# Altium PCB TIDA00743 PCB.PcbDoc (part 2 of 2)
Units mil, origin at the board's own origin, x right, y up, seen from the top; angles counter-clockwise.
Board outline 2110 x 1665 mil, 6 copper layers (Layer 1 - Top Layer, Layer 2 - GND, Layer 3 - Sensitive, Layer 4 - PWR, Layer 5 - GND, Layer 6 - Bottom Layer), stack 59.268 mil thick; 144 components, 87 nets, 420 pads, 309 vias.
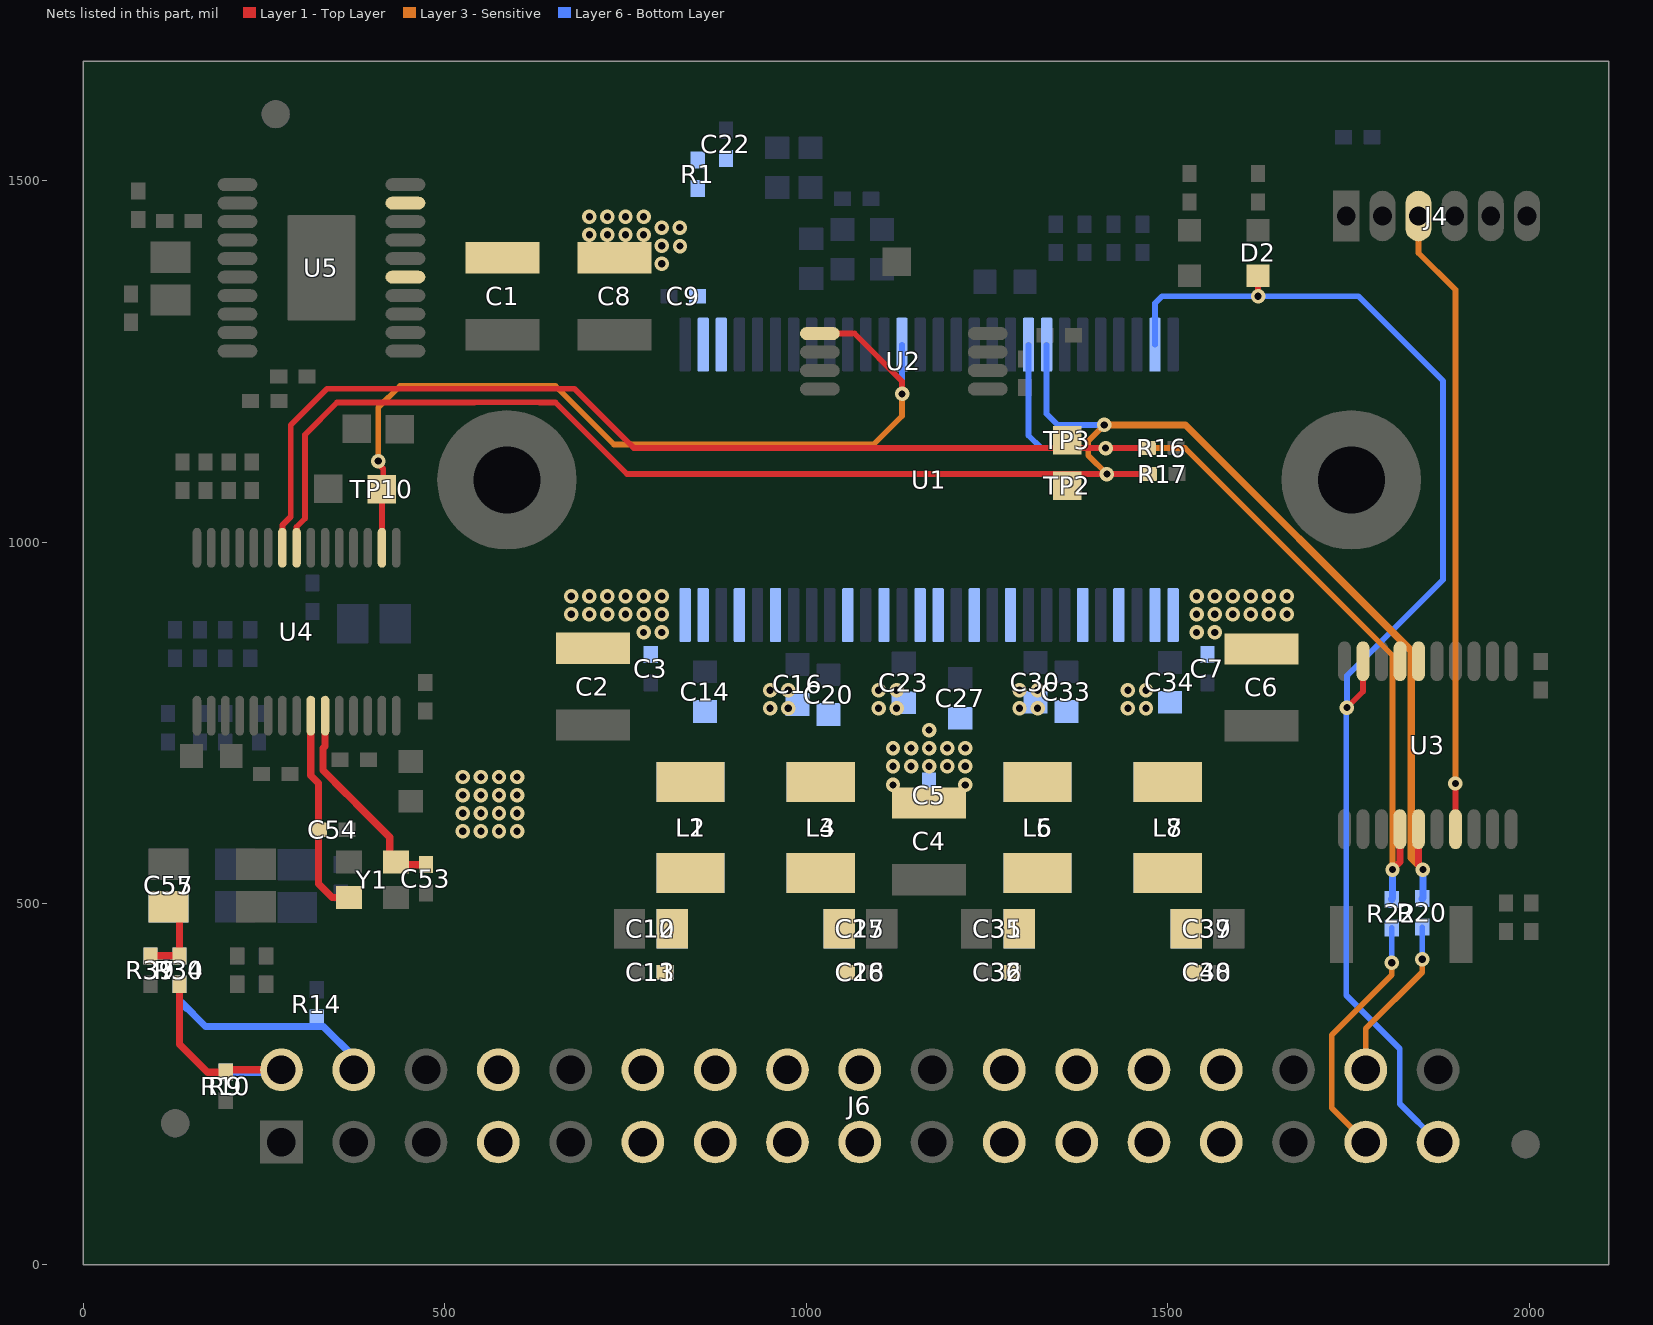
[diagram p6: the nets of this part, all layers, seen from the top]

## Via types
v1: diameter 20, hole 10, Layer 1 - Top Layer to Layer 6 - Bottom Layer, tented both sides, 287 vias
v2: diameter 39.37, hole 19.68, Layer 1 - Top Layer to Layer 6 - Bottom Layer, 12 vias
v3: diameter 19.68, hole 7.87, Layer 1 - Top Layer to Layer 6 - Bottom Layer, 6 vias
v4: diameter 20, hole 10, Layer 1 - Top Layer to Layer 6 - Bottom Layer, tented bottom, 4 vias

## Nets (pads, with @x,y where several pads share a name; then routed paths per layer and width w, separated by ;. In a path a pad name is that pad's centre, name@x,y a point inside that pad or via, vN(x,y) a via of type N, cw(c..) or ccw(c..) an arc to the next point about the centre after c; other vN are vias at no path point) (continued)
NWARN1: D2.1 J6.33 U1.27 U3.9 | length 1769.9
  Layer 1 - Top Layer w8: v1(1625,1340) D2.1@1625,1368.5 ; v1(1748,771) 1770.12,793.12 U3.9@1770.12,835.14
  Layer 6 - Bottom Layer w8: U1.27@1482.5,1273.01 1482.5,1330.5 1492,1340 v1(1625,1340) 1764,1340 1881,1223 1881,948 1748,815 v1(1748,771) ; v1@1747,770 1747,373 1821,299 1821,223.04 J6.33@1874.04,170
OUT1+: C37.1 C38.1 J6.25 J6.26 L7.2
OUT1-: C39.1 C40.1 J6.27 J6.28 L8.2
OUT1M: C34.1 L8.1 U1.32
  other v1: 1445,770 1470,770 1445,795 1470,795
OUT1P: C33.1 L7.1 U1.34
OUT2+: C31.1 C32.1 J6.21 J6.22 L5.2
OUT2-: C35.1 C36.1 J6.23 J6.24 L6.2
OUT2M: C30.1 L6.1 U1.38
  other v1: 1295,770 1320,770 1295,795 1320,795
OUT2P: C27.1 L5.1 U1.40
OUT3+: C17.1 C18.1 J6.15 J6.16 L3.2
OUT3-: C25.1 C26.1 J6.17 J6.18 L4.2
OUT3M: C23.1 L4.1 U1.45
  other v1: 1100,770 1125,770 1100,795 1125,795
OUT3P: C20.1 L3.1 U1.47
OUT4+: C10.1 C11.1 J6.11 J6.12 L1.2
OUT4-: C12.1 C13.1 J6.13 J6.14 L2.2
OUT4M: C16.1 L2.1 U1.51
  other v1: 950,770 975,770 950,795 975,795
OUT4P: C14.1 L1.1 U1.53
PVDD: C1.1 C2.1 C3.1 C4.1 C5.1 C6.1 C7.1 C8.1 C9.1 J6.7 J6.8 R1.1 U1.2 U1.29 U1.30 U1.42 U1.43 U1.55 U1.56 U5.15 U5.19
  other v1: 525,600 550,600 575,600 600,600 525,625 550,625 575,625 600,625 525,650 550,650 575,650 600,650 1120,664 1220,664 525,675 550,675 575,675 600,675 1120,690 1145,690 1170,690 1195,690 1220,690 1120,715 1145,715 1170,715 1195,715 1220,715 1170,740 775,875 800,875 1540,875 1565,875 675,900 700,900 725,900 750,900 775,900 800,900 1540,900 1565,900 1590,900 1615,900 1640,900 1665,900 675,925 700,925 725,925 750,925 775,925 800,925 1540,925 1565,925 1590,925 1615,925 1640,925 1665,925 800,1385 800,1410 825.39,1409.51 700,1425 725,1425 750,1425 775,1425 800,1435 825,1435 700,1450 725,1450 750,1450 775,1450
REAR_L: J6.2 R9.2 R10.2 R30.2 | length 313.8
  Layer 1 - Top Layer w10: R30.2@133,388.31 133,305.31 171.63,266.69 R9.2@197,266.69 ; R9.2@197,270 J6.2@274.04,270
  Layer 6 - Bottom Layer w10: R10.2@197,266.69 J6.2@270.73,266.69
REAR_L_ATTN: C55.1 R30.1 R37.2 | length 114
  Layer 1 - Top Layer w10: R37.2@93,427.69 R30.1@133,427.68 133,480.47 C55.1@118,495.47
REAR_R: J6.4 R14.1 R34.2 | length 328.8
  Layer 6 - Bottom Layer w10: 136,363 169,330 332,330 374.04,287.96 J6.4@374.04,270 ; R34.2@136,385.31 R34.2@133,388.31 133,365 143,355
REAR_R_ATTN: C57.1 R34.1 R39.2 | length 114
  Layer 6 - Bottom Layer w10: R39.2@93,427.69 R34.1@133,427.68 133,480.47 C57.1@118,495.47
SBWTCK: J4.3 U3.17 | length 869.3
  Layer 1 - Top Layer w8: v1(1898,666) 1898.07,665.93 U3.17@1898.07,602.86
  Layer 3 - Sensitive w8: J4.3@1847,1451 1847,1400 1898,1349 v1(1898,666)
SCL: R16.1 R22.2 TP3.1 U1.20 U3.14 U4.24 | length 2569
  Layer 1 - Top Layer w8: U4.24@275.31,992.14 275.31,1023.31 287,1035 287,1162 337,1212 679.4,1212 761.4,1130 v1(1414,1130) R16.1@1472.32,1130
  Layer 1 - Top Layer w10: v1(1811,547) 1821.3,557.3 U3.14@1821.3,602.86
  Layer 3 - Sensitive w8: v1@1415,1131 v1(1414,1130) 1524,1130 1811,843 v1(1811,547)
  Layer 6 - Bottom Layer w8: U1.20@1307.5,1273.01 1307.5,1147.5 1325,1130 v1(1414,1130)
  Layer 6 - Bottom Layer w10: R22.2@1810,505.79 1811,506.79 v1(1811,547)
SCL_EXT: J6.31 R22.1 | length 357.3
  Layer 3 - Sensitive w8: J6.31@1779,174.96 J6.31@1774.04,170 1727,217.04 1727,318 1810,401 v1(1810,418)
  Layer 6 - Bottom Layer w8: v1(1810,418) R22.1@1810,466.42
SCLK: TP10.1 U1.13 U2.1 U4.17 | length 1237.8
  Layer 1 - Top Layer w8: v4@408,1108.49 415,1101.49 415,1075 TP10.1@413.11,1073.11 U4.17@413.11,992.14 ; U2.1@1018.86,1288.39 1066.61,1288.39 1132.5,1222.5 v1(1132.5,1205)
  Layer 3 - Sensitive w8: v4(408,1112) 408,1186 438,1216 653,1216 734,1135 1093,1135 1132.5,1174.5 v1(1132.5,1205)
  Layer 6 - Bottom Layer w8: v1(1132.5,1205) U1.13@1132.5,1273.01
SDA: R17.1 R20.2 TP2.1 U1.21 U3.15 U4.23 | length 2619.8
  Layer 1 - Top Layer w8: U4.23@295,992.14 295,1021 306.5,1032.5 306.5,1148.5 351,1193 541.03,1193 541.49,1193.46 630.51,1193.46 630.97,1193 653,1193 752,1094 v1(1416,1094) R17.1@1473.32,1094
  Layer 1 - Top Layer w10: U3.15@1846.89,602.86 1846.89,553.11 v1(1853,547)
  Layer 3 - Sensitive w8: 1390.15,1140 1390.15,1119.85 v1(1416,1094) ; 1390.45,1139.75 1390.45,1140.3 v1(1412.12,1161.98)
  Layer 3 - Sensitive w10: v1(1412.12,1161.98) 1524.64,1161.98 1837,849.62 1837,563 v1(1853,547)
  Layer 6 - Bottom Layer w8: U1.21@1332.5,1273.01 1332.5,1177.5 1348.02,1161.98 v1(1412.12,1161.98)
  Layer 6 - Bottom Layer w10: R20.2@1852,506.69 1853,507.69 v1(1853,547)
SDA_EXT: J6.32 R20.1 | length 229.6
  Layer 3 - Sensitive w8: J6.32@1774.04,270 1774.04,327.04 1852,405 v1(1852,423)
  Layer 6 - Bottom Layer w8: v1(1852,423) R20.1@1852,467.32
U1_VBAT: C22.1 R1.2 U1.3
VOL_DN: U3.7
VOL_UP: U3.6
XI: C53.1 U4.10 Y1.1 | length 283.1
  Layer 1 - Top Layer w10: U4.10@334.37,759.86 334.37,717.65 331.5,714.79 331.5,684.19 363.69,652 364.11,652 377,639.11 377,638.69 424,591.69 424,566.09 Y1.1@432.48,557.61 ; Y1.1@436.4,553.68 C53.1@474,553.68
XO: C54.1 U4.9 Y1.3 | length 285.3
  Layer 1 - Top Layer w10: U4.9@314.5,758.08 314.5,677.15 325.32,666.33 C54.1@325.32,602 325.32,527.28 344.2,508.39 Y1.3@367.52,508.39
pads on no net: FID1.1 FID2.1 FID3.1 FID4.1 FID5.1 FID6.1 J4.1 J4.6 U3.2 U3.3 U3.4 U3.5 U3.12 U3.13 U3.18 U3.19 U4.5 U4.19 U4.20 U4.22 U5.1 U5.2 U5.5 U5.6 U5.16 U5.17 U5.18 U5.20

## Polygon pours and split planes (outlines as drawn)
GND on Layer 4 - PWR "Layer 4 - PWR - GND" (solid, remove dead copper, pour order 23): 0,0 2110,0 2110,1665 0,1665
PVDD on Layer 4 - PWR "Layer 4 - PWR - PVDD" (solid, pour order 13): 505,584 620,584 620,669 811,860 970,860 1010,820 1010,745 1099,656 1321,656 1410,745 1410,825 1445,860 1655,860 1675,880 1675,945 1600,1020 1040,1020 895,1165 875,1185 875,1210 875,1430 845,1460 690,1460 690,1350 690,1038 505,853
GND on Layer 2 - GND "Layer 2 - GND - GND" (solid, remove dead copper, pour order 21): 0,0 2110,0 2110,1665 0,1665
GND on Layer 5 - GND "Layer 2 - GND - GND" (solid, remove dead copper, pour order 19): 0,0 2110,0 2110,1665 0,1665
+3P3V on Layer 3 - Sensitive "+3P3V_L03_P010" (solid, remove dead copper, pour order 10): 517,982 517,952 461,952 445.02,936.02 445.02,982
GND on Layer 3 - Sensitive "Layer 3 - Sensitive - GND" (solid, remove dead copper, pour order 17): 0,0 2110,0 2110,1665 0,1665
GND on Layer 1 - Top Layer "Layer 1 - Top Layer - GND" (solid, remove dead copper, pour order 15): 0,0 2110,0 2110,1665 0,1665
3V3_OUT on Layer 1 - Top Layer "3V3_OUT_L01_P009" (solid, remove dead copper, pour order 9): 198,1419 88.85,1419 88.85,1458 54,1458 54,1419 54,1372 54,1332 82,1332 82,1372 147,1372 184,1409 198,1409
GND on Layer 6 - Bottom Layer "Layer 6 - Bottom Layer - GND" (solid, remove dead copper, pour order 14): 0,0 2110,0 2110,1665 0,1665
PVDD on Layer 6 - Bottom Layer "PVDD_L06_P012" (solid, remove dead copper, pour order 12): 815.21,855.09 658,855 658,960 701,1003 701,1128 634.86,1194.14 634.86,1420.55 690,1460 824.51,1460 825,1460.49 825,1399.9 793.1,1368 725,1368 725,1189.63 816,1180 816,1098.63 816,855.89

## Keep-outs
Keep-Out Layer:
  text ".Layer_Name" at 97,-758.49 h60

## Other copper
Layer 1 - Top Layer:
  rectangle net PVDD: 1149,757 1191,872.74
  region net +3P3V: 55.45,1314.74 55.45,1253.91 63.36,1246 112,1246 116,1250 116,1262 109,1269 86.18,1269 77.79,1277.39 77.79,1290.3 77.79,1318 55.45,1318
  pour cut-out: 0,1166 255.63,1166 255.63,1038.14 240.24,1022.76 230,1012.51 230,951.45 249.45,932 252,932 252,846 275.21,822.79 311,787 310.94,578.15 297.2,578.15 297.2,790.69 243,844.89 243,923.75 224,942.75 224,1019 249.45,1044.45 249.45,1149.8 242.4,1159 0,1159
  region net +3P3V: 1221.61,1302 1221.61,1255 1342,1255 1342,1298.53 1317.85,1298.53 1317.85,1401 1288.54,1401 1288.54,1302
  pour cut-out: 1963.72,1401 2029.15,1401 2029.15,1501 1963.72,1501
  pour cut-out: 1714,1401 1930.28,1401 1930.28,1501 1714,1501
  pour cut-out: 497.77,1344 398,1344 398,1522.67 497.77,1522.67
  pour cut-out: 1224,1149.51 1224,1344 956,1344 956,1266 1057.19,1266 1136.8,1149.51
  region net OUT1-: 1536,136 1611,136 1611,321.69 1548,394.25 1548,570 1442.44,570 1442.44,402.56 1536,309
  region net OUT2-: 1330,136 1330,283.69 1272,354.69 1272,570 1368,570 1368,358 1410,316 1410,136
  region net GND: 1530,818.03 1530,775 1580,725 1580,513 1562,495 1562,395 1567,390 1660,390 1690,420 1690,817.91
  region net GND: 810,818.03 810,775 760,725 760,513 778,495 778,395 773,390 680,390 650,420 650,817.91
  region net PVDD: 450,1358.02 530.02,1358.02 862.42,1358.02 862.42,1491 514,1491 514,1478 450,1478 450,1460 513,1460 527,1446 527,1389 514,1376 450,1376
  region net OUT1M: 1430,630 1430,795 1440,805 1475,805 1550,730 1550,630
  region net OUT2M: 1270,630 1370,630 1370,765 1330,805 1290,805 1270,785
  region net OUT4M: 890,630 890,670 985,765 985,800 980,805 890,805 785,700 785,630
  region net OUT3M: 1070,630 1070,700 1135,765 1135,800 1130,805 1060,805 970,715 970,630
  region net GND: 1082,390 1082,532 1120,570 1220,570 1258,532 1258,390
  region net PVDD: 1110,630 1110,720 1153.55,763.55 1186.45,763.55 1230,720 1230,630
  region net OUT4-: 908,136 908,328.05 897,371.47 897,570 792,570 792,360.05 837,290 837,136
  region net OUT3-: 1068,570 1068,365.11 1110,311.59 1110,136 1038,136 1038,288.95 972,365.11 972,415 972,570
  pour cut-out: 264,1344.04 170.23,1344.04 170.23,1519.38 264,1519.38
  pour cut-out: 116.55,721 429.33,721 429.33,802.8 252,802.8 252,953 432.97,953 432.97,1049 117.21,1049 117.34,937 229.21,937 243,923.21 243,845.24 117,845.24
  pour cut-out: 1530,1335 1615,1335 1615,1495 1530,1495
  region net PVDD: 502,943 834,943 1680,943 1680,832 834,832 625,832 625,126 522,126 522,374 502,374
  pour cut-out: 2041,882 1718.69,882 1718.69,539 1968,539 1968,795.31 2041,795.31
  pour cut-out: 775,691 775,518.39 907.39,518.39 907.39,691
  pour cut-out: 1425,691.31 1425,518.69 1557.39,518.69 1557.39,691.31
  pour cut-out: 1255,691 1255,518.39 1387.39,518.39 1387.39,691
  pour cut-out: 955,691 955,518.39 1087.39,518.39 1087.39,691
  pour cut-out: 775,691 775,518.39 907.39,518.39 907.39,691
  text ".Layer_Name" at 97,-758.49 h60
Layer 2 - GND:
  rectangle net PVDD: 516,587 612,685
  rectangle net PVDD: 1528.33,865.91 1683.13,938.56
  rectangle net PVDD: 1528.33,865.91 1683.13,938.56
  pour cut-out: 0,1166 255.63,1166 255.63,1038.14 240.24,1022.76 230,1012.51 230,951.45 249.45,932 252,932 252,846 275.21,822.79 311,787 310.94,578.15 297.2,578.15 297.2,790.69 243,844.89 243,923.75 224,942.75 224,1019 249.45,1044.45 249.45,1149.8 242.4,1159 0,1159
  pour cut-out: 1963.72,1401 2029.15,1401 2029.15,1501 1963.72,1501
  pour cut-out: 1714,1401 1929.15,1401 1929.15,1501 1714,1501
  pour cut-out: 0,1181.45 1.55,1183 224,1183 255.63,1183 255.63,1038.14 240.24,1022.76 230,1012.51 230,951.45 249.45,932 252,932 252,846 275.21,822.79 311,787 310.94,578.15 297.2,578.15 297.2,790.69 243,844.89 243,923.75 224,942.75 224,1019 249.45,1044.45 249.45,1149.8 237.03,1166 0.75,1166 0,1165.25
  text ".Layer_Name" at 97,-758.49 h60
Layer 4 - PWR:
  rectangle net PVDD: 523,136.45 624,675
  pour cut-out: 0,1166 255.63,1166 255.63,1038.14 240.24,1022.76 230,1012.51 230,951.45 249.45,932 252,932 252,846 275.21,822.79 311,787 310.94,578.15 297.2,578.15 297.2,790.69 243,844.89 243,923.75 224,942.75 224,1019 249.45,1044.45 249.45,1149.8 242.4,1159 0,1159
  pour cut-out: 1963.72,1401 2029.15,1401 2029.15,1501 1963.72,1501
  pour cut-out: 1714,1401 1930.28,1401 1930.28,1501 1714,1501
  pour cut-out: 740,1197 810,1197 810,1325 790,1325 790,1250 740,1250
  text ".Layer_Name" at 97,-758.49 h60
Layer 3 - Sensitive:
  rectangle net PVDD: 536,137.96 611,300.71
  rectangle net PVDD: 523,136.45 624,675
  rectangle net PVDD: 506.98,581.98 623.55,693.02
  pour cut-out: 0,1166 255.63,1166 255.63,1038.14 240.24,1022.76 230,1012.51 230,951.45 249.45,932 252,932 252,846 275.21,822.79 311,787 310.94,578.15 297.2,578.15 297.2,790.69 243,844.89 243,923.75 224,942.75 224,1019 249.45,1044.45 249.45,1149.8 242.4,1159 0,1159
  pour cut-out: 1714,1401 2029,1401 2030,1400 2030,1501 1714,1501
  text ".Layer_Name" at 97,-758.49 h60
Layer 5 - GND:
  rectangle net PVDD: 1528.33,865.91 1683.13,938.56
  rectangle net PVDD: 516,587 612,685
  pour cut-out: 0,1166 255.63,1166 255.63,1038.14 240.24,1022.76 230,1012.51 230,951.45 249.45,932 252,932 252,846 275.21,822.79 311,787 310.94,578.15 297.2,578.15 297.2,790.69 243,844.89 243,923.75 224,942.75 224,1019 249.45,1044.45 249.45,1149.8 242.4,1159 0,1159
  pour cut-out: 1963.72,1401 2029.15,1401 2029.15,1501 1963.72,1501
  pour cut-out: 1714,1401 1929.15,1401 1929.15,1501 1714,1501
  text ".Layer_Name" at 97,-758.49 h60
Layer 6 - Bottom Layer:
  rectangle net PVDD: 506.98,581.98 618.02,693.02
  pour cut-out: 0,1166 255.63,1166 255.63,1038.14 240.24,1022.76 230,1012.51 230,951.45 249.45,932 252,932 252,846 275.21,822.79 311,787 310.94,578.15 297.2,578.15 297.2,790.69 243,844.89 243,923.75 224,942.75 224,1019 249.45,1044.45 249.45,1149.8 242.4,1159 0,1159
  pour cut-out: 1963.72,1401 2029.15,1401 2029.15,1501 1963.72,1501
  pour cut-out: 1714,1401 1930.28,1401 1930.28,1501 1714,1501
  region net OUT1+: 1511,136 1433,136 1433,337.73 1443,356.4 1443,570 1548,570 1548,366.59 1511,309.13 1511,280
  region net OUT2+: 1272,570 1272,353 1237,290.69 1237,136 1312,136 1312,289.29 1368.87,370.01 1368,459 1368,570
  pour cut-out: 805,937 805,955 1640,955 1640,937
  region net GND: 1530,818.03 1530,775 1580,725 1580,513 1562,495 1562,395 1567,390 1660,390 1690,420 1690,817.91
  region net GND: 810,818.03 810,775 760,725 760,513 778,495 778,395 773,390 680,390 650,420 650,817.91
  region net PVDD: 1529,830 1529,861 1474,861 1474,937 1673,937 1690,920 1690,830
  region net PVDD: 833,830 833,860 866,860 866,937 516,937 501,922 501,830
  region net OUT1M: 1441,937 1441,843 1441,817 1452.5,805.5 1475,805.5 1491,789.5 1491,767 1483.5,759.5 1434.5,759.5 1424,770 1424,803 1424,851 1424,937
  region net OUT2P: 1231,837 1246.24,821.76 1246.24,793.24 1225,772 1225,743 1255,713 1255,630 1370,630 1370,695 1320,745 1275,745 1268,752 1268,833 1253,848 1231,848
  region net OUT4P: 920,839 920,630 785,630 785,700 899,814 899,888 915.5,888 915.5,843.5
  region net OUT4M: 966,937 966,856 963,853 963,820.72 963,803 985,803 985,765 980,760 938,760 938,820 938,850 949,861 949,937
  region net OUT3P: 1070,630 1070,744 1077,751 1077,840 1055,840 1055,787 970,702 970,630
  region net GND: 1082,390 1258,390 1258,532 1220,570 1120,570 1082,532
  region net PVDD: 1149,937 1149,864 1161,852 1161,760 1155,754 1155,726 1110,726 1110,655 1230,655 1230,726 1185,726 1185,765 1185,780 1185,798 1179,804 1179,848 1191,860 1191,937
  region net NetC34_2: 1449,937 1449,843 1452,840 1452,818 1497,818 1497,849 1466,849 1466,851 1466,937
  region net NetC33_2: 1366,937 1366,830 1366,820 1343,820 1343,845 1349,851 1349,937
  region net OUT1P: 1374,937 1374,849 1384,839 1384,797 1384,781 1350,781 1350,750 1377,723 1410,690 1410,630 1550,630 1550,695 1500,745 1425,745 1408,762 1408,839 1391,856 1391,937
  region net OUT2M: 1291,937 1291,853 1291,816 1301.5,805.5 1325,805.5 1335.5,795 1335.5,770 1325,759.5 1319.5,759.5 1283,759.5 1283,798 1275,806 1275,937
  region net NetC30_2: 1299,937 1299,843 1302,840 1302,820 1327,820 1327,840 1316,851 1316,937
  region net NetC27_2: 1216,937 1216,843 1216,820 1196,820 1196,836 1199,839 1199,937
  region net OUT2P: 1224,937 1224,844 1231,837 1252,837 1252,849 1241,860 1241,937
  region net NetC14_2: 891,937 891,843 872,824 872,814.65 851,814.65 851,828 874,851 874,937
  region net NetC16_2: 974,937 974,843 977,840 977,820 1002,820 1002,840 991,851 991,937
  region net NetC20_2: 1041,937 1041,855 1038,852 1038,820 1024,820 1024,851 1024,937
  region net OUT3P: 1049,937 1049,843 1055,837 1055,820 1077,820 1077,840 1066,851 1066,937
  region net NetC23_2: 1124,937 1124,843 1127,840 1127,820 1152,820 1152,840 1141,851 1141,937
  region net OUT3M: 1116,937 1116,861 1111,856 1111,805.2 1135,805.2 1135,765 1130,760 1088,760 1088,820 1088,849 1099,860 1099,937
  region net OUT4+: 737,136 737,314.4 792,360.67 792,380.56 792,570 897.56,570 897.56,361.76 809,273.2 809,136
  region net OUT3+: 1007,136 1007,303 1068,364 1068,570 972,570 972,380 941,349 941,136
  region net GND: 1562,495 1562,390 1625,390 1640,405 1640,480 1625,495
  region net GND: 1270,1340 1266,1336 1266,1214 1224,1214 1224,1425 1270,1425
  region net PVDD: 849,1235 849,1317 837,1329 837,1353 823,1367 680,1367 680,1450 690,1460 828,1460 828,1501 866,1501 866,1235
  region net U1_VBAT: 874,1235 874,1419 874,1516 840,1516 840,1543 874,1543 908,1543 908,1480 891,1463 891,1235
  region net PVDD: 625,838.22 501,838.22 501,374 520.71,374 520.71,121 625,121
  pour cut-out: 1425,691.31 1425,518.69 1557.39,518.69 1557.39,691.31
  pour cut-out: 1425,691.31 1425,518.69 1557.39,518.69 1557.39,691.31
  pour cut-out: 1255,691 1255,518.39 1376,518.39 1376,691
  pour cut-out: 955,691 955,518.39 1087.39,518.39 1087.39,691
  pour cut-out: 775,691 775,518.39 907.39,518.39 907.39,691
  text ".Layer_Name" at 97,-758.49 h60

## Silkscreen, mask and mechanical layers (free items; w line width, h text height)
Top Overlay:
  lines w5: 97,351 117,371 ; 215,1151 226,1132
  text "MCLK" at 1090.11,1352.17 h30 r90
  text "FAULT" at 1490,1255 h30
  text "WARN" at 1585,1255 h30
  text "DOUT" at 352.09,1184.46 h30
  text "SCL" at 1280,1130 h30
  text "LRCLK" at 483,1111 h30 r90
  text "DOUT2" at 322,1100 h30 r90
  text "SDA" at 1271,1066 h30
  text "SCLK" at 466,1020 h30 r90
  text ".PRJ_Number" at 740,997 h65
  text "REV '.PCB_Rev'" at 1111,993 h65
  text "RESET" at 1762,351 h30
  text ".Layer_Name" at 97,-758.49 h60
Bottom Overlay:
  lines w5: 123,335 136,363
  text ".Layer_Name" at 97,-758.49 h60
Top Paste:
  text ".Layer_Name" at 97,-758.49 h60
Bottom Paste:
  text ".Layer_Name" at 97,-758.49 h60
Top Solder:
  region: 50,119 2108.18,119 2110,120.82 2110,0 0,0 0,118.79 49.79,118.79
  text ".Layer_Name" at 97,-758.49 h60
  text ".Layer_Name" at 97,-758.49 h60
Bottom Solder:
  region: 50,119 2108.18,119 2110,120.82 2110,0 0,0 0,118.79 49.79,118.79
  text ".Layer_Name" at 97,-758.49 h60
Drill Guide:
  text ".Layer_Name" at 97,-758.49 h60
M1 Board Outline:
  the board outline again, w10
  text ".Layer_Name" at 97,-758.49 h60
M2 Board Dimensions:
  rectangle: -130,-175 -5,-50
  rectangle: -5,-300 370,-175
  lines w7: -130,-175 870,-175 ; -5,-300 -5,-50 ; 120,-300 120,-50 ; 370,-300 370,-50 ; 620,-300 620,-50 ; -130,-300 870,-300 870,-50 -130,-50 -130,-300
  text "2 Places" at 2617.66,322 h60 r90
  text ".Layer_Name" at 97,-758.49 h60
M3 3D STEP Top:
  text ".Layer_Name" at 97,-758.49 h60
M4 3D STEP Bottom:
  text ".Layer_Name" at 97,-758.49 h60
M5 Assembly Top:
  lines w10: -772,-830.17 5828,-830.17 ; -772,-626.83 5830,-626.83 ; -772,-423.5 -772,-1033.5 3233,-1033.5 5830,-1033.5 5830,-423.5 -771.5,-423.5 -771.5,-1033.5 804,-1033.5 ; 1693,-1033.5 1693,-423.5 ; 2960,-626.83 2960,-423.5 ; 3800,-626.83 3800,-423.5 ; 4422,-1040 4422,-837.17
  text "COMPONENTS MARKED 'DNP' SHOULD NOT BE POPULATED." at -89.5,2118.5 h60
  text "ASSEMBLY VARIANT:" at -90,2003 h60
  text ".VariantName" at 946,2003 h60
  text "PCB VIEWED FROM TOP SIDE" at -708.5,-555.67 h60
  text "BOARD #:" at 1768,-555.67 h60
  text ".PRJ_Number" at 2313.5,-555.67 h60
  text "REV:" at 3158,-555.67 h60
  text ".PCB_Rev" at 3449.5,-555.67 h60
  text "SVN REV:" at 3996,-555.67 h60
  text ".VersionControl_RevNumber" at 4502,-555.67 h60
  text "TID #:" at 1768,-759 h60
  text ".TID" at 2313.5,-759 h60
  text "PLOT NAME =" at -708.5,-964.34 h60
  text ".plot_File_Name" at 97,-964.34 h60
  text "GENERATED    :" at 1770,-964.34 h60
  text ".Print_Date" at 2639.5,-964.34 h60
  text ".Print_Time" at 3368.5,-964.34 h60
  text "TEXAS INSTRUMENTS" at 4633,-964.34 h60
M6 Assembly Bottom:
  lines w10: -772.5,-627.33 5829.5,-627.33 ; -770.5,-830.67 5829.5,-830.67 ; 635.5,-1040.5 635.5,-837.67 ; 1257.5,-627.33 1257.5,-424 ; 2097.5,-627.33 2097.5,-424 ; 3364.5,-1034 3364.5,-424 ; 4253.5,-1034 5829,-1034 5829,-424 -772.5,-424 -772.5,-1034 1824.5,-1034 5829.5,-1034 5829.5,-424
  text "COMPONENTS MARKED 'DNP' SHOULD NOT BE POPULATED." at 5622,-218 h60
  text ".VariantName" at 4578,-334 h60
  text "ASSEMBLY VARIANT:" at 5617,-334 h60
  text ".VersionControl_RevNumber" at 555.5,-556.17 h60
  text "SVN REV:" at 1061.5,-556.17 h60
  text ".PCB_Rev" at 1608,-556.17 h60
  text "REV:" at 1899.5,-556.17 h60
  text ".PRJ_Number" at 2744,-556.17 h60
  text "BOARD #:" at 3289.5,-556.17 h60
  text "PCB VIEWED FROM BOTTOM SIDE" at 5766,-556.17 h60
  text ".TID" at 2744,-759.5 h60
  text "TID #:" at 3289.5,-759.5 h60
  text "TEXAS INSTRUMENTS" at 424.5,-964.84 h60
  text ".Print_Time" at 1689,-964.84 h60
  text ".Print_Date" at 2418,-964.84 h60
  text "GENERATED    :" at 3287.5,-964.84 h60
  text ".plot_File_Name" at 4960.5,-964.84 h60
  text "PLOT NAME =" at 5766,-964.84 h60
M9 Title Sheet:
  drawing of 57 lines, arcs and shapes, not listed
  text "1" at 259.84,8136.5 h70
  text "2" at 2755.5,8136.5 h70
  text "3" at 5244.84,8136.5 h70
  text "4" at 7751.51,8136.5 h70
  text "5" at 10250.5,8136.5 h70
  text "6" at 12755.5,8136.5 h70
  text "A" at -896.5,6993.5 h70
  text "A" at 13903.5,6993.5 h70
  text "B" at -896.5,4613.5 h70
  text "B" at 13903.5,4613.5 h70
  text "C" at -896.5,2238.5 h70
  text "C" at 13903.5,2238.5 h70
  text "PROJECT TITLE:" at 10863.5,377.5 h45
  text ".PRJ_Title" at 10913.5,244.17 h70
  text "DESIGNED FOR:" at 10863.5,76.5 h45
  text ".PRJ_Customer" at 10913.5,-63.5 h70
  text "D" at -896.5,-131.5 h70
  text "D" at 13903.5,-131.5 h70
  text "FILE NAME:" at 10863.5,-223.5 h45
  text ".PCB_File_Name_No_Path" at 10913.5,-343.5 h70
  text "Texas Instruments (TI) and/or its licensors do not warrant the accuracy or completeness of this specification" at 5894,-505.34 h45
  text "ENGINEER:" at 10863.5,-513.5 h45
  text "LAYOUT BY:" at 12368.5,-513.5 h45
  text "or any information contained therein. TI and/or its licensors do not warrant that this design will meet" at 5849.01,-618 h45
  text ".PRJ_Engineer" at 10913.5,-668.49 h70
  text "M. Knapp" at 12385,-672 h60
  text "the specifications, will be suitable for your application or fit for any particular purpose, or will operate in" at 5849.01,-730.67 h45
  text ".Layer_Name" at 97,-758.49 h60
  text "ALTIUM DESIGNER VERSION:" at 12368.5,-823.5 h45
  text "an implementation. TI and/or its licensors do not warrant that the design is production worthy. You should" at 5849.01,-843.33 h45
  text "completely validate and test your design implementation to confirm the system functionality for your application." at 5894,-956 h45
  text ".print_Scale" at 10913.5,-956.83 h70
  text ".Application_BuildNumber" at 12419,-956.83 h70
  text "1" at 259.84,-1163.5 h70
  text "2" at 2755.5,-1163.5 h70
  text "3" at 5244.84,-1163.5 h70
  text "4" at 7751.51,-1163.5 h70
  text "5" at 10250.5,-1163.5 h70
  text "6" at 12755.5,-1163.5 h70
M10 Fab Notes:
  drawing of 173 lines, arcs and shapes, not listed
  text "DESIGN INFORMATION" at 11898.02,6301 h60
  text "MIN. TRACK WIDTH:" at 11253.46,6121 h60
  text "7" at 12349.7,6121 h60
  text "MIL" at 12504.46,6121 h60
  text "MIN. CLEARANCE:" at 11253.46,5989 h60
  text "0.2" at 12289.7,5989 h60
  text "mm" at 12504.46,5989 h60
  text "MIN. VIA PAD SIZE:" at 11253.46,5857 h60
  text "20" at 12319.71,5857 h60
  text "MIL" at 12504.46,5857 h60
  text "0.05mm (2MIL)" at 11948.46,5715.29 h60
  text "MINIMUM ANNULAR RING" at 10924.23,5711 h60
  text "EXTERNAL" at 12656.46,5711 h60
  text "PER" at 11124.23,5593 h60
  text "IPC-D-275 CLASS 2 LEVEL C" at 11344.23,5593 h60
  text "MIL, HOLES" at 12832.46,5480.71 h60
  text "+/-" at 12440,5480 h60
  text "+/-" at 13294,5480 h60
  text "REGISTRATION TOLERANCES:" at 10924.23,5475 h60
  text "METAL" at 12124,5475 h60
  text "5" at 12700.2,5475 h60
  text "3" at 13533.2,5475 h60
  text "MIL" at 13649.46,5475 h60
  text "+/-" at 13294,5362 h60
  text "HOLE SIZE TOLERANCE (UNLESS OTHERWISE SPECIFIED):" at 10924.23,5357 h60
  text "3" at 13533.2,5357 h60
  text "MIL" at 13649.46,5357 h60
  text "MATERIAL:" at 10849.46,5147.54 h60
  text "FR-4 High Tg" at 11835.9,5007.21 h60
  text "FR-408" at 11270.46,4998.64 h60
  text "OTHER" at 12758.46,4998.64 h60
  text "X" at 11681,4995 h60
  text "62 MIL (1.6mm) +/-10%" at 11590.56,4835.92 h60
  text "THICKNESS:" at 10924.23,4831.64 h60
  text "X" at 11462.4,4831.64 h60
  text "OTHER" at 12875.46,4831.64 h60
  text "TOLERANCE:" at 10924.23,4673.64 h60
  text "X" at 11763.53,4673.64 h60
  text "ANSI IPC-6012 TYPE 3 CLASS 2" at 11950.48,4673.64 h60
  text "OTHER +/-" at 11950.46,4517.64 h60
  text "BOW & TWIST:" at 10924.23,4360.64 h60
  text "X" at 11763.53,4360.64 h60
  text "ANSI IPC-6012 TYPE 3 CLASS 2" at 11950.48,4360.64 h60
  text "OTHER +/-" at 11950.46,4202.13 h60
  text "DRILLING:" at 10849.46,4063.64 h60
  text "REFERENCE:" at 10924.23,3946.64 h60
  text "X" at 11572.46,3946.64 h60
  text "AS SHOWN" at 11759.46,3946.64 h60
  text "X" at 12473.46,3946.64 h60
  text "NC_DRILL FILES" at 12610.46,3946.64 h60
  text "PTH MIN COPPER THICKNESS:" at 10924.23,3788.64 h60
  text "X" at 12274.46,3788.64 h60
  text "1MIL" at 12411.46,3788.64 h60
  text "OTHER" at 12908.46,3788.64 h60
  text "BOARD FINISH:" at 10849.46,3629.64 h60
  text "SILKSCREEN:" at 11004.68,3511.64 h60
  text "X" at 11953.46,3511.64 h60
  text "TOP" at 12079.46,3511.64 h60
  text "X" at 12463.46,3511.64 h60
  text "BOTTOM" at 12590.46,3511.64 h60
  text "SILKSCREEN COLOR:" at 11004.68,3344.64 h60
  text "X" at 11952.42,3344.64 h60
  text "WHITE" at 12079.46,3344.64 h60
  text "OTHER" at 12590.46,3344.64 h60
  text "X" at 12083.42,3185.44 h60
  text "GREEN" at 12210.46,3185.44 h60
  text "OTHER" at 12828.46,3185.44 h60
  text "SOLDER RESIST COLOR:" at 11004.68,3174.64 h60
  text "X" at 12083.42,3015.44 h60
  text "MATTE" at 12210.46,3015.44 h60
  text "SEMI-GLOSS" at 12828,3014.8 h60
  text "IMMERSION GOLD (ENIG)" at 11910.46,2826.92 h60
  text "ENEPIG" at 13248,2823.64 h60
  text "SURFACE FINISH:" at 10849.46,2822.64 h60
  text "X" at 11723.51,2822.64 h60
  text "IMM. TIN/SILVER OR EQUIV" at 11179,2665.64 h60
  text "OTHER" at 12610.46,2665.64 h60
  text "ARRAY/PANEL:" at 10849.46,2486.64 h60
  text "CUT AND TRIM PER M1 BOARD OUTLINE" at 11910.46,2482.35 h60
  text "N.C. ROUTE" at 11910.46,2330.64 h60
  text "X" at 12589.46,2330.64 h60
  text "V. SCORE" at 12776.46,2330.64 h60
  text "CERTIFICATION:" at 10849.46,2193.64 h60
  text "MATERIALS AND WORKMANSHIP FOR ALL PCBS" at 11574.46,2193.64 h60
  text "TO MEET OR EXCEED THE REQUIREMENTS OF:" at 11574.46,2095.64 h60
  text "X" at 11200.96,1959.13 h60
  text "ANSI IPC-A-600F CLASS ->" at 11339.96,1959.13 h60
  text "X" at 12979.02,1959.13 h60
  text "2" at 13097.96,1959.14 h60
  text "1" at 12782.96,1957.64 h60
  text "3" at 13451.96,1957.64 h60
  text "X" at 12015.02,1799.64 h60
  text "RoHS" at 12151.96,1799.64 h60
  text "OTHER" at 12796.36,1799.64 h60
  text "PER ORDER" at 13193.42,1799.64 h60
  text "ALL BOARDS MUST MEET OR EXCEED UL94-V0 REQUIREMENTS." at 10877,1634 h60
  text "PCB MUST BEAR THE UL94V-0 UL REGISTERED MATERIAL ID NUMBER" at 10877,1514 h60
  text "ADDITIONAL REQUIREMENTS:" at 10849.46,1340.64 h60
  text "MICROSECTION:" at 10924.23,1225.64 h60
  text "YES" at 11829.96,1225.64 h60
  text "REQUIRED" at 12691.46,1069.49 h60
  text "BARE BOARD ELEC. TEST:" at 10924.23,1066.64 h60
  text "NONE" at 12229.96,1066.64 h60
  text "X" at 12564.46,1066.64 h60
  text "PER ORDER" at 13283.46,1066.64 h60
  text ".Layer_Name" at 97,-758.49 h60
M11 Gerber Information:
  lines w10: -772,-830.17 5828,-830.17 ; -772,-626.83 5830,-626.83 ; -772,-423.5 -772,-1033.5 3233,-1033.5 5830,-1033.5 5830,-423.5 -771.5,-423.5 -771.5,-1033.5 804,-1033.5 ; 1693,-1033.5 1693,-423.5 ; 2960,-626.83 2960,-423.5 ; 3800,-626.83 3800,-423.5 ; 4422,-1040 4422,-837.17
  text "ALL ARTWORK VIEWED FROM TOP SIDE" at -708.5,-555.67 h60
  text "BOARD #:" at 1768,-555.67 h60
  text ".PRJ_Number" at 2313.5,-555.67 h60
  text "REV:" at 3158,-555.67 h60
  text ".PCB_Rev" at 3449.5,-555.67 h60
  text "SVN REV:" at 3996,-555.67 h60
  text ".VersionControl_RevNumber" at 4502,-555.67 h60
  text "LAYER NAME =" at -708.5,-758.49 h60
  text "TID #:" at 1768,-759 h60
  text ".TID" at 2313.5,-759 h60
  text "PLOT NAME =" at -708.5,-964.34 h60
  text ".plot_File_Name" at 97,-964.34 h60
  text "GENERATED    :" at 1770,-964.34 h60
  text ".Print_Date" at 2639.5,-964.34 h60
  text ".Print_Time" at 3368.5,-964.34 h60
  text "TEXAS INSTRUMENTS" at 4633,-964.34 h60
M12 Stackup:
  drawing of 399 lines, arcs and shapes, not listed
  text "Layer" at 5837.5,7932.5 h60
  text "Name" at 6247.41,7932.5 h60
  text "Material" at 7657,7932.5 h60
  text "Thickness" at 8516.77,7932.5 h60
  text "Constant" at 9166.6,7932.5 h60
  text "Board Layer Stack" at 9736.47,7932.5 h60
  text "1" at 5837.5,7812.5 h60
  text "Top Overlay" at 6247.41,7812.5 h60
  text "2" at 5837.5,7692.5 h60
  text "Top Solder" at 6247.41,7692.5 h60
  text "Solder Resist" at 7657,7692.5 h60
  text "0.40mil" at 8516.77,7692.5 h60
  text "3.5" at 9166.6,7692.5 h60
  text "3" at 5837.5,7572.5 h60
  text "Layer 1 - Top Layer" at 6247.41,7572.5 h60
  text "Copper" at 7657,7572.5 h60
  text "1.40mil" at 8516.77,7572.5 h60
  text "4" at 5837.5,7452.5 h60
  text "Dielectric 1" at 6247.41,7452.5 h60
  text "370HR" at 7657,7452.5 h60
  text "5.20mil" at 8516.77,7452.5 h60
  text "4.2" at 9166.6,7452.5 h60
  text "5" at 5837.5,7332.5 h60
  text "Layer 2 - GND" at 6247.41,7332.5 h60
  text "Copper" at 7657,7332.5 h60
  text "1.42mil" at 8516.77,7332.5 h60
  text "6" at 5837.5,7212.5 h60
  text "Dielectric 2" at 6247.41,7212.5 h60
  text "370HR" at 7657,7212.5 h60
  text "5.20mil" at 8516.77,7212.5 h60
  text "4.2" at 9166.6,7212.5 h60
  text "7" at 5837.5,7092.5 h60
  text "Layer 3 - Sensitive" at 6247.41,7092.5 h60
  text "Copper" at 7657,7092.5 h60
  text "1.42mil" at 8516.77,7092.5 h60
  text "8" at 5837.5,6972.5 h60
  text "Dielectric 3" at 6247.41,6972.5 h60
  text "370HR" at 7657,6972.5 h60
  text "30.00mil" at 8516.77,6972.5 h60
  text "4.2" at 9166.6,6972.5 h60
  text "9" at 5837.5,6852.5 h60
  text "Layer 4 - PWR" at 6247.41,6852.5 h60
  text "Copper" at 7657,6852.5 h60
  text "1.42mil" at 8516.77,6852.5 h60
  text "10" at 5837.5,6732.5 h60
  text "Dielectric 4" at 6247.41,6732.5 h60
  text "370HR" at 7657,6732.5 h60
  text "5.20mil" at 8516.77,6732.5 h60
  text "4.2" at 9166.6,6732.5 h60
  text "11" at 5837.5,6612.5 h60
  text "Layer 5 - GND" at 6247.41,6612.5 h60
  text "Copper" at 7657,6612.5 h60
  text "1.42mil" at 8516.77,6612.5 h60
  text "12" at 5837.5,6492.5 h60
  text "Dielectric 5" at 6247.41,6492.5 h60
  text "370HR" at 7657,6492.5 h60
  text "5.20mil" at 8516.77,6492.5 h60
  text "4.2" at 9166.6,6492.5 h60
  text "13" at 5837.5,6372.5 h60
  text "Layer 6 - Bottom Layer" at 6247.41,6372.5 h60
  text "Copper" at 7657,6372.5 h60
  text "1.40mil" at 8516.77,6372.5 h60
  text "14" at 5837.5,6252.5 h60
  text "Bottom Solder" at 6247.41,6252.5 h60
  text "Solder Resist" at 7657,6252.5 h60
  text "0.40mil" at 8516.77,6252.5 h60
  text "3.5" at 9166.6,6252.5 h60
  text "15" at 5837.5,6132.5 h60
  text "Bottom Overlay" at 6247.41,6132.5 h60
  text ".Layer_Name" at 97,-758.49 h60
M13 Component Bodies Top:
  text ".Layer_Name" at 97,-758.49 h60
M14 Component Bodies Bottom:
  text ".Layer_Name" at 97,-758.49 h60
M15 Courtyards Top:
  text ".Layer_Name" at 97,-758.49 h60
M16 Courtyards Bottom:
  text ".Layer_Name" at 97,-758.49 h60
Drill Drawing:
  circle w10: c3083.82,493.52 r16.6
  circle w10: c3083.82,493.52 r27.67
  lines w10: 3056.16,590.35 3111.49,590.35 3111.49,645.68 3056.16,645.68 3056.16,590.35 ; 3056.16,714.85 3056.16,728.68 3069.99,742.52 3056.16,756.35 3056.16,770.18 3069.99,770.18 3083.82,756.35 3097.66,770.18 3111.49,770.18 3111.49,756.35 3097.66,742.52 3111.49,728.68 3111.49,714.85 3097.66,714.85 3083.82,728.68 3069.99,714.85 3056.16,714.85 ; 3056.16,853.18 3069.99,853.18 3069.99,839.35 3097.66,839.35 3097.66,853.18 3111.49,853.18 3111.49,880.85 3097.66,880.85 3097.66,894.68 3069.99,894.68 3069.99,880.85 3056.16,880.85 3056.16,853.18 ; 3056.16,1019.18 3111.49,1019.18 3083.82,963.85 3056.16,1019.18 ; 3056.16,1102.18 3069.99,1102.18 3083.82,1088.35 3097.66,1102.18 3111.49,1102.18 3097.66,1116.02 3111.49,1129.85 3097.66,1129.85 3083.82,1143.68 3069.99,1129.85 3056.16,1129.85 3069.99,1116.02 3056.16,1102.18 ; 3067.23,1008.12 3100.43,1008.12 3083.82,974.92 3067.23,1008.12 ; 3067.23,1107.72 3075.52,1107.72 3083.82,1099.42 3092.12,1107.72 3100.43,1107.72 3092.12,1116.02 3100.43,1124.32 3092.12,1124.32 3083.82,1132.62 3075.52,1124.32 3067.23,1124.32 3075.52,1116.02 3067.23,1107.72
  lines w12: 3006,428.5 4984.44,428.5 ; 3006,1175.5 4984.44,1175.5 ; 3344.01,304 3344.01,1300 ; 3676.17,304 3676.17,1300 ; 4312.65,304 4312.65,1300 ; 4571.85,304 4571.85,1300 ; 3006,304 4984.44,304 4984.44,1300 3006,1300 3006,304
  text "Symbol" at 3080.7,1212.85 h72
  text "Quantity" at 3381.36,1212.85 h72
  text "Finished Hole Size" at 3713.52,1212.85 h72
  text "Plated" at 4350,1212.85 h72
  text "Hole Type" at 4609.2,1212.85 h72
  text "6" at 3381.36,1088.35 h60
  text "7.87mil (0.200mm)" at 3713.52,1088.35 h60
  text "PTH" at 4350,1088.35 h60
  text "Round" at 4609.2,1088.35 h60
  text "291" at 3381.36,963.85 h60
  text "10.00mil (0.254mm)" at 3713.52,963.85 h60
  text "PTH" at 4350,963.85 h60
  text "Round" at 4609.2,963.85 h60
  text "12" at 3381.36,839.35 h60
  text "19.69mil (0.500mm)" at 3713.52,839.35 h60
  text "PTH" at 4350,839.35 h60
  text "Round" at 4609.2,839.35 h60
  text "6" at 3381.36,714.85 h60
  text "26.00mil (0.660mm)" at 3713.52,714.85 h60
  text "PTH" at 4350,714.85 h60
  text "Round" at 4609.2,714.85 h60
  text "34" at 3381.36,590.35 h60
  text "39.37mil (1.000mm)" at 3713.52,590.35 h60
  text "PTH" at 4350,590.35 h60
  text "Round" at 4609.2,590.35 h60
  text "2" at 3381.36,465.85 h60
  text "92.52mil (2.350mm)" at 3713.52,465.85 h60
  text "PTH" at 4350,465.85 h60
  text "Round" at 4609.2,465.85 h60
  text "351 Total" at 3381.36,341.35 h60
  text ".Layer_Name" at 97,-758.49 h60

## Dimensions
0,1665 to 2110,1665 on M2 Board Dimensions
-130,-300 to 870,-300 on M2 Board Dimensions
0,1665 to 1754,1086 on M2 Board Dimensions
0,0 to 0,1665 on M2 Board Dimensions
2110,0 to 1754,1086 on M2 Board Dimensions
0,1665 to 586,1086 on M2 Board Dimensions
